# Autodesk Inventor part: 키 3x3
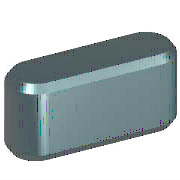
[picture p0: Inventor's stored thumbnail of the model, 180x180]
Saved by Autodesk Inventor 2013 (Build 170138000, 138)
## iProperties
Created: 2012-02
Part Number: 키 3x3
Material: 강철, 연강
Description: 키 및 해당 키홈
Document SubType Name: Modeling
Standard: KS B 1311
Designer: mduedu
Standards Organization: KS
Language: ko-KR
Size Designation: 3 x 3 x 12
Categories: <MemberInstance><Categories><Category DisplayName="샤프트 부품" InternalName="7f7aeb1f-a693-4053-b835-cee3144e0d98" Mnemonic="SHFT"><Category DisplayName="키" Interna
Density: 1 g/cm^3
IsCustomPart: 1
Author: mduedu
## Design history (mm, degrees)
workplane "Work Plane1"
workplane "Work Plane2"
sketch "스케치1"
  geometry: L1 (1.5, 1.5)-(10.5, 1.5); L2 (10.5, -1.5)-(1.5, -1.5); L3 (0, 9.4)-(0, -7.4) reference; L4 (-5, 0)-(30, 0) reference; L5 (12, 0)-(12, 7); A1 r 1.5 centre (1.5, 0) between (1.5, 1.5) and (1.5, -1.5); A2 r 1.5 centre (10.5, 0) between (10.5, -1.5) and (10.5, 1.5)
  constraints: 6 end point, 5 point on circle, 4 tangent, 3 point on line, 2 centre point, 1 horizontal, 1 parallel, 1 perpendicular
  dimensions: "d0" = 1.5 radius of A1 (= 0.5 x PB); "d13" = 1.5 radius of A2 (= 0.5 x PB); "d14" = 12 distance between parallel lines of L5 L3 (= NLG)
extrude "본체1" new body sketch "스케치1" taper "d3" = 0 deg; stored distance "d4" = 10
workplane "Work Plane3"
body "Solid1"
chamfer "모따기1" distance "d8" = 0.25 (= PHH); stored, may be unused: second distance "d9" = 0.25 (= PHH), angle "d15" = 45 deg
other parameters: "d1" = -1.8 (= -PNT), "d2" = 1.2 (= PH - PNT), "NLG" = 12 [user parameter; used in 3 equation terms], "PB" = 3 [user parameter; used in 2 equation terms], "PNT" = 1.8 [user parameter; used in 2 equation terms], "PH" = 3 [user parameter; used in 1 equation term], "PHH" = 0.25 [user parameter; used in 2 equation terms], "d10" = 0, "d16" = 0, "d17" = 0, "d18" = 0, "WDMIN" = 8 [user parameter], "PLB2" = 12 (= NLG) [user parameter], "PLB1" = 12 (= NLG) [user parameter], "RR" = 0.08 [user parameter], "PUEB" = 1.4 [user parameter]
